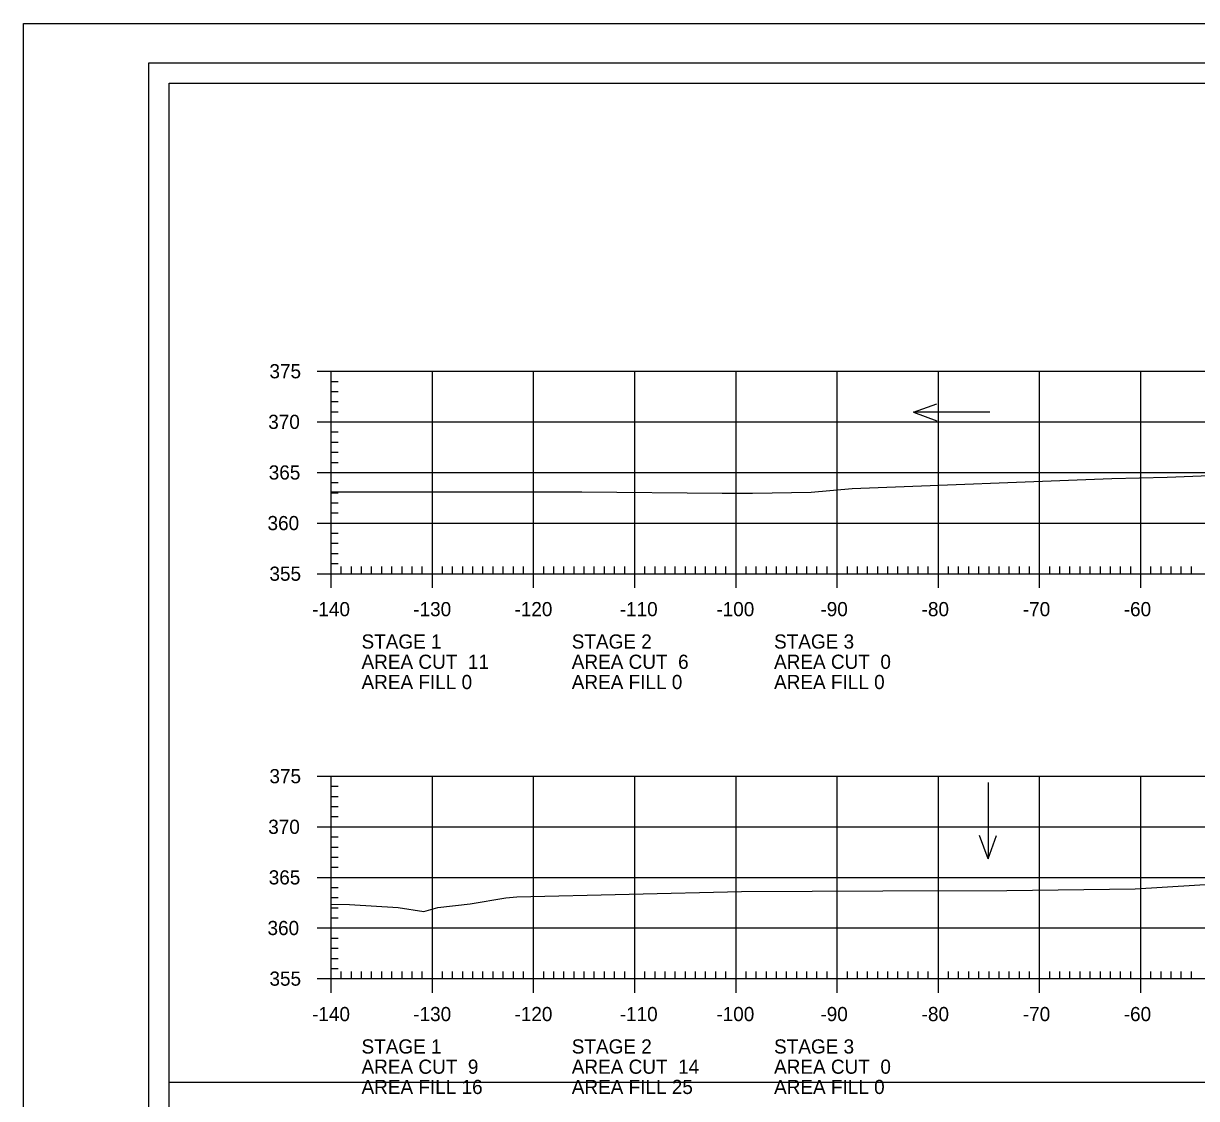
# Model space of a CAD drawing. Extents: x 1368910 to 1369601, y 380116 to 380950.
# Drawn here: x 1368909.8 to 1369025.7, y 380630.9 to 380737.1 of the extents above; entities that cross this region are included whole.
import ezdxf

# ---------------------------------------------------------------- set-up
doc = ezdxf.new("R2010")
doc.units = 0
for name, color, linetype in [('R_Axis', 7, 'Continuous'), ('R_Axis Annot', 7, 'Continuous'), ('R_Border', 7, 'Continuous'), ('R_Exist Surface', 7, 'Continuous'), ('R_Grid', 7, 'Continuous'), ('R_No Plot', 7, 'Continuous'), ('R_Water Annot', 7, 'Continuous')]:
    doc.layers.add(name, color=color, linetype=linetype)

msp = doc.modelspace()

# ---------------------------------------------------------------- linework, layer by layer
at = {"layer": 'R_Axis'}
for p, q in [((1368938.84, 380702.76), (1368941.64, 380702.76)), ((1368940.24, 380682.76), (1368940.24, 380702.76)), ((1368940.24, 380701.76), (1368940.94, 380701.76)), ((1368940.24, 380700.76), (1368940.94, 380700.76)), ((1368940.24, 380699.76), (1368940.94, 380699.76)), ((1368940.24, 380698.76), (1368940.94, 380698.76)), ((1368938.84, 380697.76), (1368941.64, 380697.76)), ((1368940.24, 380696.76), (1368940.94, 380696.76)), ((1368940.24, 380695.76), (1368940.94, 380695.76)), ((1368940.24, 380694.76), (1368940.94, 380694.76)), ((1368940.24, 380693.76), (1368940.94, 380693.76)), ((1368938.84, 380692.76), (1368941.64, 380692.76)), ((1368940.24, 380691.76), (1368940.94, 380691.76)), ((1368940.24, 380690.76), (1368940.94, 380690.76)), ((1368940.24, 380689.76), (1368940.94, 380689.76)), ((1368938.84, 380687.76), (1368941.64, 380687.76)), ((1368940.24, 380688.76), (1368940.94, 380688.76)), ((1368940.24, 380686.76), (1368940.94, 380686.76)), ((1368940.24, 380685.76), (1368940.94, 380685.76)), ((1368940.24, 380684.76), (1368940.94, 380684.76)), ((1368940.24, 380681.36), (1368940.24, 380684.16)), ((1368940.24, 380683.76), (1368940.94, 380683.76)), ((1368941.24, 380682.76), (1368941.24, 380683.46)), ((1368942.24, 380682.76), (1368942.24, 380683.46)), ((1368943.24, 380682.76), (1368943.24, 380683.46)), ((1368944.24, 380682.76), (1368944.24, 380683.46)), ((1368945.24, 380682.76), (1368945.24, 380683.46)), ((1368946.24, 380682.76), (1368946.24, 380683.46)), ((1368947.24, 380682.76), (1368947.24, 380683.46)), ((1368948.24, 380682.76), (1368948.24, 380683.46)), ((1368949.24, 380682.76), (1368949.24, 380683.46)), ((1368950.24, 380681.36), (1368950.24, 380684.16)), ((1368951.24, 380682.76), (1368951.24, 380683.46)), ((1368952.24, 380682.76), (1368952.24, 380683.46)), ((1368953.24, 380682.76), (1368953.24, 380683.46)), ((1368954.24, 380682.76), (1368954.24, 380683.46)), ((1368955.24, 380682.76), (1368955.24, 380683.46)), ((1368956.24, 380682.76), (1368956.24, 380683.46)), ((1368957.24, 380682.76), (1368957.24, 380683.46)), ((1368958.24, 380682.76), (1368958.24, 380683.46)), ((1368959.24, 380682.76), (1368959.24, 380683.46)), ((1368960.24, 380681.36), (1368960.24, 380684.16)), ((1368961.24, 380682.76), (1368961.24, 380683.46)), ((1368962.24, 380682.76), (1368962.24, 380683.46)), ((1368963.24, 380682.76), (1368963.24, 380683.46)), ((1368964.24, 380682.76), (1368964.24, 380683.46)), ((1368965.24, 380682.76), (1368965.24, 380683.46)), ((1368966.24, 380682.76), (1368966.24, 380683.46)), ((1368967.24, 380682.76), (1368967.24, 380683.46)), ((1368968.24, 380682.76), (1368968.24, 380683.46)), ((1368969.24, 380682.76), (1368969.24, 380683.46)), ((1368970.24, 380681.36), (1368970.24, 380684.16)), ((1368971.24, 380682.76), (1368971.24, 380683.46)), ((1368972.24, 380682.76), (1368972.24, 380683.46)), ((1368973.24, 380682.76), (1368973.24, 380683.46)), ((1368974.24, 380682.76), (1368974.24, 380683.46)), ((1368975.24, 380682.76), (1368975.24, 380683.46)), ((1368976.24, 380682.76), (1368976.24, 380683.46)), ((1368977.24, 380682.76), (1368977.24, 380683.46)), ((1368978.24, 380682.76), (1368978.24, 380683.46)), ((1368979.24, 380682.76), (1368979.24, 380683.46)), ((1368980.24, 380681.36), (1368980.24, 380684.16)), ((1368981.24, 380682.76), (1368981.24, 380683.46)), ((1368982.24, 380682.76), (1368982.24, 380683.46)), ((1368983.24, 380682.76), (1368983.24, 380683.46)), ((1368984.24, 380682.76), (1368984.24, 380683.46)), ((1368985.24, 380682.76), (1368985.24, 380683.46)), ((1368986.24, 380682.76), (1368986.24, 380683.46)), ((1368987.24, 380682.76), (1368987.24, 380683.46)), ((1368988.24, 380682.76), (1368988.24, 380683.46)), ((1368989.24, 380682.76), (1368989.24, 380683.46)), ((1368990.24, 380681.36), (1368990.24, 380684.16)), ((1368991.24, 380682.76), (1368991.24, 380683.46)), ((1368992.24, 380682.76), (1368992.24, 380683.46)), ((1368993.24, 380682.76), (1368993.24, 380683.46)), ((1368994.24, 380682.76), (1368994.24, 380683.46)), ((1368995.24, 380682.76), (1368995.24, 380683.46)), ((1368996.24, 380682.76), (1368996.24, 380683.46)), ((1368997.24, 380682.76), (1368997.24, 380683.46)), ((1368998.24, 380682.76), (1368998.24, 380683.46)), ((1368999.24, 380682.76), (1368999.24, 380683.46)), ((1369000.24, 380681.36), (1369000.24, 380684.16)), ((1369001.24, 380682.76), (1369001.24, 380683.46)), ((1369002.24, 380682.76), (1369002.24, 380683.46)), ((1369003.24, 380682.76), (1369003.24, 380683.46)), ((1369004.24, 380682.76), (1369004.24, 380683.46)), ((1369005.24, 380682.76), (1369005.24, 380683.46)), ((1369006.24, 380682.76), (1369006.24, 380683.46)), ((1369007.24, 380682.76), (1369007.24, 380683.46)), ((1369008.24, 380682.76), (1369008.24, 380683.46)), ((1369009.24, 380682.76), (1369009.24, 380683.46)), ((1369010.24, 380681.36), (1369010.24, 380684.16)), ((1369011.24, 380682.76), (1369011.24, 380683.46)), ((1369012.24, 380682.76), (1369012.24, 380683.46)), ((1369013.24, 380682.76), (1369013.24, 380683.46)), ((1369014.24, 380682.76), (1369014.24, 380683.46)), ((1369015.24, 380682.76), (1369015.24, 380683.46)), ((1369016.24, 380682.76), (1369016.24, 380683.46)), ((1369017.24, 380682.76), (1369017.24, 380683.46)), ((1369018.24, 380682.76), (1369018.24, 380683.46)), ((1369019.24, 380682.76), (1369019.24, 380683.46)), ((1369020.24, 380681.36), (1369020.24, 380684.16)), ((1369021.24, 380682.76), (1369021.24, 380683.46)), ((1369022.24, 380682.76), (1369022.24, 380683.46)), ((1369023.24, 380682.76), (1369023.24, 380683.46)), ((1369024.24, 380682.76), (1369024.24, 380683.46)), ((1369025.24, 380682.76), (1369025.24, 380683.46)), ((1368938.84, 380682.76), (1368941.64, 380682.76)), ((1368940.24, 380682.76), (1369220.24, 380682.76)), ((1368938.84, 380662.76), (1368941.64, 380662.76)), ((1368940.24, 380642.76), (1368940.24, 380662.76)), ((1368940.24, 380661.76), (1368940.94, 380661.76)), ((1368940.24, 380660.76), (1368940.94, 380660.76)), ((1368940.24, 380659.76), (1368940.94, 380659.76)), ((1368940.24, 380658.76), (1368940.94, 380658.76)), ((1368938.84, 380657.76), (1368941.64, 380657.76)), ((1368940.24, 380656.76), (1368940.94, 380656.76)), ((1368940.24, 380655.76), (1368940.94, 380655.76)), ((1368940.24, 380654.76), (1368940.94, 380654.76)), ((1368940.24, 380653.76), (1368940.94, 380653.76)), ((1368938.84, 380652.76), (1368941.64, 380652.76)), ((1368940.24, 380651.76), (1368940.94, 380651.76)), ((1368940.24, 380650.76), (1368940.94, 380650.76)), ((1368940.24, 380649.76), (1368940.94, 380649.76)), ((1368940.24, 380648.76), (1368940.94, 380648.76)), ((1368938.84, 380647.76), (1368941.64, 380647.76)), ((1368940.24, 380646.76), (1368940.94, 380646.76)), ((1368940.24, 380645.76), (1368940.94, 380645.76)), ((1368940.24, 380644.76), (1368940.94, 380644.76)), ((1368940.24, 380641.36), (1368940.24, 380644.16)), ((1368940.24, 380643.76), (1368940.94, 380643.76)), ((1368950.24, 380641.36), (1368950.24, 380644.16)), ((1368960.24, 380641.36), (1368960.24, 380644.16)), ((1368970.24, 380641.36), (1368970.24, 380644.16)), ((1368980.24, 380641.36), (1368980.24, 380644.16)), ((1368990.24, 380641.36), (1368990.24, 380644.16)), ((1369000.24, 380641.36), (1369000.24, 380644.16)), ((1369010.24, 380641.36), (1369010.24, 380644.16)), ((1369020.24, 380641.36), (1369020.24, 380644.16)), ((1368938.84, 380642.76), (1368941.64, 380642.76)), ((1368940.24, 380642.76), (1369220.24, 380642.76)), ((1368941.24, 380642.76), (1368941.24, 380643.46)), ((1368942.24, 380642.76), (1368942.24, 380643.46)), ((1368943.24, 380642.76), (1368943.24, 380643.46)), ((1368944.24, 380642.76), (1368944.24, 380643.46)), ((1368945.24, 380642.76), (1368945.24, 380643.46)), ((1368946.24, 380642.76), (1368946.24, 380643.46)), ((1368947.24, 380642.76), (1368947.24, 380643.46)), ((1368948.24, 380642.76), (1368948.24, 380643.46)), ((1368949.24, 380642.76), (1368949.24, 380643.46)), ((1368951.24, 380642.76), (1368951.24, 380643.46)), ((1368952.24, 380642.76), (1368952.24, 380643.46)), ((1368953.24, 380642.76), (1368953.24, 380643.46)), ((1368954.24, 380642.76), (1368954.24, 380643.46)), ((1368955.24, 380642.76), (1368955.24, 380643.46)), ((1368956.24, 380642.76), (1368956.24, 380643.46)), ((1368957.24, 380642.76), (1368957.24, 380643.46)), ((1368958.24, 380642.76), (1368958.24, 380643.46)), ((1368959.24, 380642.76), (1368959.24, 380643.46)), ((1368961.24, 380642.76), (1368961.24, 380643.46)), ((1368962.24, 380642.76), (1368962.24, 380643.46)), ((1368963.24, 380642.76), (1368963.24, 380643.46)), ((1368964.24, 380642.76), (1368964.24, 380643.46)), ((1368965.24, 380642.76), (1368965.24, 380643.46)), ((1368966.24, 380642.76), (1368966.24, 380643.46)), ((1368967.24, 380642.76), (1368967.24, 380643.46)), ((1368968.24, 380642.76), (1368968.24, 380643.46)), ((1368969.24, 380642.76), (1368969.24, 380643.46)), ((1368971.24, 380642.76), (1368971.24, 380643.46)), ((1368972.24, 380642.76), (1368972.24, 380643.46)), ((1368973.24, 380642.76), (1368973.24, 380643.46)), ((1368974.24, 380642.76), (1368974.24, 380643.46)), ((1368975.24, 380642.76), (1368975.24, 380643.46)), ((1368976.24, 380642.76), (1368976.24, 380643.46)), ((1368977.24, 380642.76), (1368977.24, 380643.46)), ((1368978.24, 380642.76), (1368978.24, 380643.46)), ((1368979.24, 380642.76), (1368979.24, 380643.46)), ((1368981.24, 380642.76), (1368981.24, 380643.46)), ((1368982.24, 380642.76), (1368982.24, 380643.46)), ((1368983.24, 380642.76), (1368983.24, 380643.46)), ((1368984.24, 380642.76), (1368984.24, 380643.46)), ((1368985.24, 380642.76), (1368985.24, 380643.46)), ((1368986.24, 380642.76), (1368986.24, 380643.46)), ((1368987.24, 380642.76), (1368987.24, 380643.46)), ((1368988.24, 380642.76), (1368988.24, 380643.46)), ((1368989.24, 380642.76), (1368989.24, 380643.46)), ((1368991.24, 380642.76), (1368991.24, 380643.46)), ((1368992.24, 380642.76), (1368992.24, 380643.46)), ((1368993.24, 380642.76), (1368993.24, 380643.46)), ((1368994.24, 380642.76), (1368994.24, 380643.46)), ((1368995.24, 380642.76), (1368995.24, 380643.46)), ((1368996.24, 380642.76), (1368996.24, 380643.46)), ((1368997.24, 380642.76), (1368997.24, 380643.46)), ((1368998.24, 380642.76), (1368998.24, 380643.46)), ((1368999.24, 380642.76), (1368999.24, 380643.46)), ((1369001.24, 380642.76), (1369001.24, 380643.46)), ((1369002.24, 380642.76), (1369002.24, 380643.46)), ((1369003.24, 380642.76), (1369003.24, 380643.46)), ((1369004.24, 380642.76), (1369004.24, 380643.46)), ((1369005.24, 380642.76), (1369005.24, 380643.46)), ((1369006.24, 380642.76), (1369006.24, 380643.46)), ((1369007.24, 380642.76), (1369007.24, 380643.46)), ((1369008.24, 380642.76), (1369008.24, 380643.46)), ((1369009.24, 380642.76), (1369009.24, 380643.46)), ((1369011.24, 380642.76), (1369011.24, 380643.46)), ((1369012.24, 380642.76), (1369012.24, 380643.46)), ((1369013.24, 380642.76), (1369013.24, 380643.46)), ((1369014.24, 380642.76), (1369014.24, 380643.46)), ((1369015.24, 380642.76), (1369015.24, 380643.46)), ((1369016.24, 380642.76), (1369016.24, 380643.46)), ((1369017.24, 380642.76), (1369017.24, 380643.46)), ((1369018.24, 380642.76), (1369018.24, 380643.46)), ((1369019.24, 380642.76), (1369019.24, 380643.46)), ((1369021.24, 380642.76), (1369021.24, 380643.46)), ((1369022.24, 380642.76), (1369022.24, 380643.46)), ((1369023.24, 380642.76), (1369023.24, 380643.46)), ((1369024.24, 380642.76), (1369024.24, 380643.46)), ((1369025.24, 380642.76), (1369025.24, 380643.46))]:
    msp.add_line(p, q, dxfattribs=at)
at = {"layer": 'R_Border'}
for p, q in [((1368922.24, 380733.22), (1369238.42, 380733.22)), ((1368922.24, 380527.76), (1368922.24, 380733.22))]:
    msp.add_line(p, q, dxfattribs=at)
at = {"layer": 'R_Exist Surface'}
for points in [[(1368940.24, 380690.86), (1368965.01, 380690.84), (1368978.88, 380690.72), (1368980.41, 380690.72), (1368981.86, 380690.73), (1368987.65, 380690.82), (1368991.73, 380691.18), (1369017.38, 380692.15), (1369022.84, 380692.31), (1369044.73, 380693.14)], [(1368940.24, 380650.11), (1368942.05, 380650.09), (1368946.87, 380649.77), (1368949.39, 380649.4), (1368950.79, 380649.77), (1368953.97, 380650.14), (1368957.49, 380650.73), (1368958.59, 380650.85), (1368980.78, 380651.37), (1368994.74, 380651.44), (1369007.01, 380651.45), (1369019.68, 380651.63), (1369035.11, 380652.6)]]:
    msp.add_lwpolyline(points, dxfattribs=at)
at = {"layer": 'R_Grid'}
for p, q in [((1368940.24, 380702.76), (1369220.24, 380702.76)), ((1368940.24, 380682.76), (1368940.24, 380702.76)), ((1368950.24, 380682.76), (1368950.24, 380702.76)), ((1368960.24, 380682.76), (1368960.24, 380702.76)), ((1368970.24, 380682.76), (1368970.24, 380702.76)), ((1368980.24, 380682.76), (1368980.24, 380702.76)), ((1368990.24, 380682.76), (1368990.24, 380702.76)), ((1369000.24, 380682.76), (1369000.24, 380702.76)), ((1369010.24, 380682.76), (1369010.24, 380702.76)), ((1369020.24, 380682.76), (1369020.24, 380702.76)), ((1368940.24, 380697.76), (1369220.24, 380697.76)), ((1368940.24, 380692.76), (1369220.24, 380692.76)), ((1368940.24, 380687.76), (1369220.24, 380687.76)), ((1368940.24, 380682.76), (1369220.24, 380682.76)), ((1368940.24, 380662.76), (1369220.24, 380662.76)), ((1368940.24, 380642.76), (1368940.24, 380662.76)), ((1368950.24, 380642.76), (1368950.24, 380662.76)), ((1368960.24, 380642.76), (1368960.24, 380662.76)), ((1368970.24, 380642.76), (1368970.24, 380662.76)), ((1368980.24, 380642.76), (1368980.24, 380662.76)), ((1368990.24, 380642.76), (1368990.24, 380662.76)), ((1369000.24, 380642.76), (1369000.24, 380662.76)), ((1369010.24, 380642.76), (1369010.24, 380662.76)), ((1369020.24, 380642.76), (1369020.24, 380662.76)), ((1368940.24, 380657.76), (1369220.24, 380657.76)), ((1368940.24, 380652.76), (1369220.24, 380652.76)), ((1368940.24, 380647.76), (1369220.24, 380647.76)), ((1368940.24, 380642.76), (1369220.24, 380642.76))]:
    msp.add_line(p, q, dxfattribs=at)
at = {"layer": 'R_No Plot'}
for points in [[(1368909.84, 380737.11), (1369243.18, 380737.11), (1369243.18, 380523.78), (1368909.84, 380523.78)], [(1369236.42, 380632.49), (1368924.24, 380632.49), (1368924.24, 380731.22), (1369173.78, 380731.22), (1369173.78, 380721.34), (1369191.32, 380721.34), (1369215.42, 380721.34), (1369215.42, 380699.01), (1369236.42, 380699.01)], [(1368924.24, 380731.22), (1369173.78, 380731.22), (1369173.78, 380721.34), (1369191.32, 380721.34), (1369215.42, 380721.34), (1369215.42, 380699.01), (1369236.42, 380699.01), (1369236.42, 380529.76), (1368924.24, 380529.76)]]:
    msp.add_lwpolyline(points, close=True, dxfattribs=at)
at = {"layer": 'R_Water Annot'}
for p, q in [((1368997.78, 380698.7), (1369000.09, 380699.54)), ((1369005.33, 380698.7), (1368997.78, 380698.7)), ((1368997.78, 380698.7), (1369000.09, 380697.86)), ((1369005.15, 380662.14), (1369005.15, 380654.6)), ((1369005.15, 380654.6), (1369004.31, 380656.91)), ((1369005.15, 380654.6), (1369005.99, 380656.91))]:
    msp.add_line(p, q, dxfattribs=at)

# ---------------------------------------------------------------- texts
at = {"layer": 'R_Axis Annot'}
for s, p in [('375', (1368934.14, 380702.06)), ('370', (1368934.02, 380697.06)), ('365', (1368934.07, 380692.06)), ('360', (1368933.95, 380687.06)), ('355', (1368934.14, 380682.06)), ('-140', (1368938.35, 380678.56)), ('-130', (1368948.35, 380678.56)), ('-120', (1368958.35, 380678.56)), ('-110', (1368968.75, 380678.56)), ('-100', (1368978.3, 380678.56)), ('-90', (1368988.58, 380678.56)), ('-80', (1368998.58, 380678.56)), ('-70', (1369008.58, 380678.56)), ('-60', (1369018.55, 380678.56)), ('STAGE 1', (1368943.24, 380675.36)), ('STAGE 2', (1368964.01, 380675.36)), ('STAGE 3', (1368984, 380675.36)), ('AREA CUT  11', (1368943.24, 380673.36)), ('AREA CUT  6', (1368964.01, 380673.36)), ('AREA CUT  0', (1368984, 380673.36)), ('AREA FILL 0', (1368943.24, 380671.36)), ('AREA FILL 0', (1368964.01, 380671.36)), ('AREA FILL 0', (1368984, 380671.36)), ('375', (1368934.14, 380662.06)), ('370', (1368934.02, 380657.06)), ('365', (1368934.07, 380652.06)), ('360', (1368933.95, 380647.06)), ('355', (1368934.14, 380642.06)), ('-140', (1368938.35, 380638.56)), ('-130', (1368948.35, 380638.56)), ('-120', (1368958.35, 380638.56)), ('-110', (1368968.75, 380638.56)), ('-100', (1368978.3, 380638.56)), ('-90', (1368988.58, 380638.56)), ('-80', (1368998.58, 380638.56)), ('-70', (1369008.58, 380638.56)), ('-60', (1369018.55, 380638.56)), ('STAGE 1', (1368943.24, 380635.36)), ('STAGE 2', (1368964.01, 380635.36)), ('STAGE 3', (1368984, 380635.36)), ('AREA CUT  9', (1368943.24, 380633.36)), ('AREA CUT  14', (1368964.01, 380633.36)), ('AREA CUT  0', (1368984, 380633.36)), ('AREA FILL 16', (1368943.24, 380631.36)), ('AREA FILL 25', (1368964.01, 380631.36)), ('AREA FILL 0', (1368984, 380631.36))]:
    msp.add_text(s, height=1.4, dxfattribs=at).set_placement(p)

doc.saveas('drawing.dxf')
